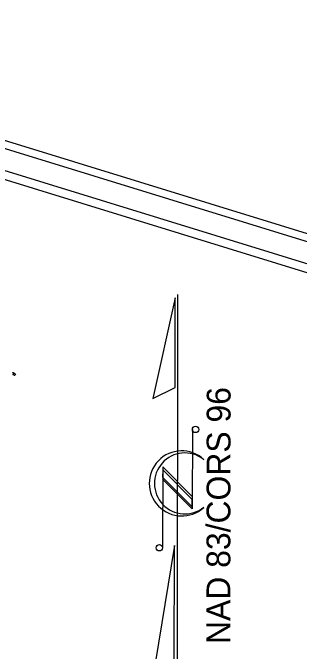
# Model space of a CAD drawing. Extents: x 1347947 to 1350662, y 1027710 to 1030532.
# Drawn here: x 1348690.9 to 1348859.2, y 1029792.5 to 1030167.4 of the extents above; entities that cross this region are included whole.
import ezdxf

# ---------------------------------------------------------------- set-up
doc = ezdxf.new("R2010")
doc.units = 0
for name, color, linetype in [('Old_Level_20', 7, 'Continuous'), ('Sheet North Arrow CELL', 7, 'Continuous'), ('Sheet Plot Border Inside CELL', 7, 'Continuous'), ('Sheet Plot Border Outside CELL', 7, 'Continuous'), ('Sheet Title CELL', 7, 'Continuous')]:
    doc.layers.add(name, color=color, linetype=linetype)

msp = doc.modelspace()

# ---------------------------------------------------------------- linework, layer by layer
at = {"layer": 'Old_Level_20'}
msp.add_lwpolyline([(1348691.11, 1029955.08), (1348691.51, 1029955.4), (1348691.58, 1029955.49), (1348691.45, 1029955.69), (1348691.03, 1029956.03), (1348691.01, 1029956.16), (1348691.19, 1029956.2), (1348692.17, 1029955.49), (1348692.41, 1029955.33), (1348692.46, 1029954.96), (1348692.39, 1029954.68), (1348692.22, 1029954.45), (1348691.95, 1029954.45), (1348691.67, 1029954.64), (1348691.24, 1029954.74), (1348691.16, 1029954.8), (1348691.09, 1029955.06), (1348691.12, 1029955.12)], dxfattribs=at)
at = {"layer": 'Sheet North Arrow CELL'}
for p, q in [((1348787.6, 1029774.4), (1348787.96, 1030001.9)), ((1348796.41, 1029922.72), (1348796.34, 1029876.03)), ((1348802.82, 1029905.31), (1348803.07, 1029905.14)), ((1348778.98, 1029900.73), (1348778.91, 1029853.27)), ((1348796.35, 1029883.31), (1348778.98, 1029900.73)), ((1348778.98, 1029899.01), (1348778.97, 1029894.74)), ((1348796.35, 1029881.59), (1348778.98, 1029899.01)), ((1348796.34, 1029877.32), (1348778.97, 1029894.74)), ((1348778.97, 1029894.74), (1348796.34, 1029877.32)), ((1348796.34, 1029876.03), (1348778.97, 1029893.45)), ((1348796.34, 1029877.32), (1348796.35, 1029881.59))]:
    msp.add_line(p, q, dxfattribs=at)
for points in [[(1348786.38, 1029999.91), (1348773.3, 1029940.85), (1348786.3, 1029947.41)], [(1348785.87, 1029854.55), (1348772.87, 1029774.42), (1348785.76, 1029784.55)]]:
    msp.add_lwpolyline(points, close=True, dxfattribs=at)
for centre in [(1348798.27, 1029922.68), (1348777.05, 1029853.2)]:
    msp.add_circle(centre, 1.86, dxfattribs=at)
for centre, radius, start, end in [((1348790.2, 1029890.99), 19.11, 47.7505, 312.3046), ((1348792.05, 1029891), 17.91, 53.0056, 308.5392)]:
    msp.add_arc(centre, radius, start, end, dxfattribs=at)
at = {"layer": 'Sheet Plot Border Inside CELL'}
msp.add_lwpolyline([(1348980.53, 1028253.25), (1349471, 1029845.94), (1348462.64, 1030156.47), (1347972.16, 1028563.78)], close=True, dxfattribs=at)
at = {"layer": 'Sheet Plot Border Outside CELL'}
msp.add_lwpolyline([(1348442.51, 1030167.38), (1347946.88, 1028557.97), (1348998.14, 1028234.22), (1349493.77, 1029843.63)], close=True, dxfattribs=at)
at = {"layer": 'Sheet Title CELL'}
for points in [[(1349455.32, 1029837.69), (1348470.95, 1030140.83)], [(1349272.28, 1029888.83), (1348474.25, 1030134.58)]]:
    msp.add_lwpolyline(points, dxfattribs=at)

# ---------------------------------------------------------------- texts
at = {"layer": 'Sheet North Arrow CELL'}
msp.add_text('NAD 83/CORS 96', height=14.0001, rotation=89.9105, dxfattribs=at).set_placement((1348818.64, 1029796.7))

doc.saveas('drawing.dxf')
